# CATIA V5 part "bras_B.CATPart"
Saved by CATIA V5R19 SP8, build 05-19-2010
Part number: bras_B
Bounding box of the stored display mesh (mm): x -17.5 to 17.5, y -17.5 to 17.5, z -17.358 to 287.417
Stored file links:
  G:\EU_thinkMotion\CFAO_2010\MMS_groupe3\MMS_groupe3\A reprendre\mmugnier\Systeme_Cric_Y\Systeme_Cric_Y\bras_B.CATPart
  C:\Users\matthieu\Desktop\CFAO\Systeme_Cric_Y\Cric_Y.CATProduct
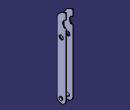
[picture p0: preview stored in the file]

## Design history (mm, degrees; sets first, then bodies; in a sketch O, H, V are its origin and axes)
Set1
  Plane1 "Plan de symetrie": linked copy from another document
  Plane2 "Plan inter bas": linked copy from another document
  Line1 "Axe 2": linked copy from another document
  Line2 "Axe 5": linked copy from another document
  Plane3 "Plan inter gauche": linked copy from another document
  Plane4 "Plan inter droit": linked copy from another document
  Line3 "Axe 4": linked copy from another document
  Plane5 "Plan exter gauche": linked copy from another document
  Plane6 "Plan exter droit": linked copy from another document
Body1 (main body)
  Sketch1 on Plane1, origin (0, 0, 0), H (0, 1, 0), V (0, 0, 1)
    line L1 (-17.5, 250) -> (-17.5, 0)
    point P2 (-17.5, 0)
    arc A1 centre (0, 0) radius 17.5 from (-17.5, 0) to (17.5, 0) ccw
    point P3 (0, 0)
    line L2 (17.5, 0) -> (17.5, 287.4166)
    arc A2 centre (20, 250) radius 37.5 from (17.5, 287.4166) to (-17.5, 250) ccw
    point P5 (20, 250)
    reference intersected line E1 through (-1.5144, -17.4343) direction (0.9962, -0.0865) from Plane2
    reference projected point E2 (0, 0) from Line1
    reference projected point E3 (20, 250) from Line2
    coincidence: P2 H, P3 E2, E3 P5
    vertical: L1 V, L2 V
    tangency: A1 L1, L1 A2, A1 E1, L2 A1
  Sketch2 on xy-plane, origin (0, 0, 0), H (1, 0, 0), V (0, 1, 0)
    line L1 (11.5, 17.5) -> (14.5, 17.5)
    line L2 (14.5, 17.5) -> (14.5, -14.5)
    arc A1 centre (11.5, -14.5) radius 3 from (14.5, -14.5) to (11.5, -17.5) cw
    line L3 (11.5, -17.5) -> (-11.5, -17.5)
    arc A2 centre (-11.5, -14.5) radius 3 from (-11.5, -17.5) to (-14.5, -14.5) cw
    line L4 (-14.5, -14.5) -> (-14.5, 17.5)
    point P9 (-14.5, 17.5)
    line L5 (-14.5, 17.5) -> (-11.5, 17.5)
    line L6 (-11.5, 17.5) -> (-11.5, -14.5)
    line L7 (-11.5, -14.5) -> (11.5, -14.5)
    line L8 (11.5, -14.5) -> (11.5, 17.5)
    reference projected point E1 (0, 17.5) from Sketch1.L2
    reference projected point E2 (0, -17.5) from Sketch1.L1
    reference intersected line E3 through (14.5, 0) direction (0, 1) from Plane3
    reference intersected line E4 through (-14.5, 0) direction (0, 1) from Plane4
    length L1 = 3
    horizontal: L1 H, L5 H, L7 H
    vertical: L2 V, L6 V, L8 V
    tangency: A1 L2, L3 A1, A2 L3, L4 A2
    coincidence: P9 L1, L1 E1, L3 E2, L2 E3, E4 L4
    parallelism: L3 L7
  SolidCombine1: FirstComponentProfile Sketch2, FirstComponentDirection Sketch2, SecondComponentProfile Sketch1, SecondComponentDirection Sketch1
  Sketch3 on face of SolidCombine1 from Sketch2.L2, origin (14.5, 0, 0), H (0, 1, 0), V (0, 0, 1)
    circle A1 centre (20, 250) radius 15
    point P1 (20, 250)
    circle A2 centre (0, 200) radius 8
    point P2 (0, 200)
    circle A3 centre (0, 0) radius 6
    point P3 (0, 0)
    reference projected point E1 (0, 0) from Line1
    reference projected point E2 (0, 200) from Line3
    reference projected point E3 (20, 250) from Line2
    radius A3 = 6
    radius A2 = 8
    radius A1 = 15
    coincidence: P3 E1, E2 P2, P1 E3
  Pocket1: profile Sketch3, direction (-1, 0, 0), through (limit type 3)
  Sketch4 on face of SolidCombine1 from Sketch2.L2, origin (14.5, 0, 0), H (0, 1, 0), V (0, 0, 1)
    projected circle E1 centre (0, 0) radius 6 from edge [face of SolidCombine1 from Sketch2.L2 | face of Pocket1 from Sketch3.A3]
  Pad1: profile Sketch4, direction (1, 0, 0), up to Plane5, opposite side up to Plane6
